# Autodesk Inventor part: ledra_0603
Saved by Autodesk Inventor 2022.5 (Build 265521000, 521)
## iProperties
Created: 2024-12
Part Number: ledra_0603
Material: Generic
Document SubType Name: Modeling
Designer: AdminForWorker
Density: 1 g/cm^3
Appearance: Default
Title: ledra_0603 v1
Author: AdminForWorker
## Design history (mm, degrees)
feature "Body9"
feature "Body10"
feature "Body11"
feature "Body12"
feature "Body13"
body "Solid1"
body "Solid2"
body "Solid3"
body "Solid4"
body "Solid5"
